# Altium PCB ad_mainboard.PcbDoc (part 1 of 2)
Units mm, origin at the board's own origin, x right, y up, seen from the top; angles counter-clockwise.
Board outline 51.7 x 87.6 mm, 4 copper layers (Top Layer, Layer 1, Layer 2, Bottom Layer), stack 0.568 mm thick; 187 components, 104 nets, 568 pads, 376 vias.
Unrouted connection lines stored in the file: 1.
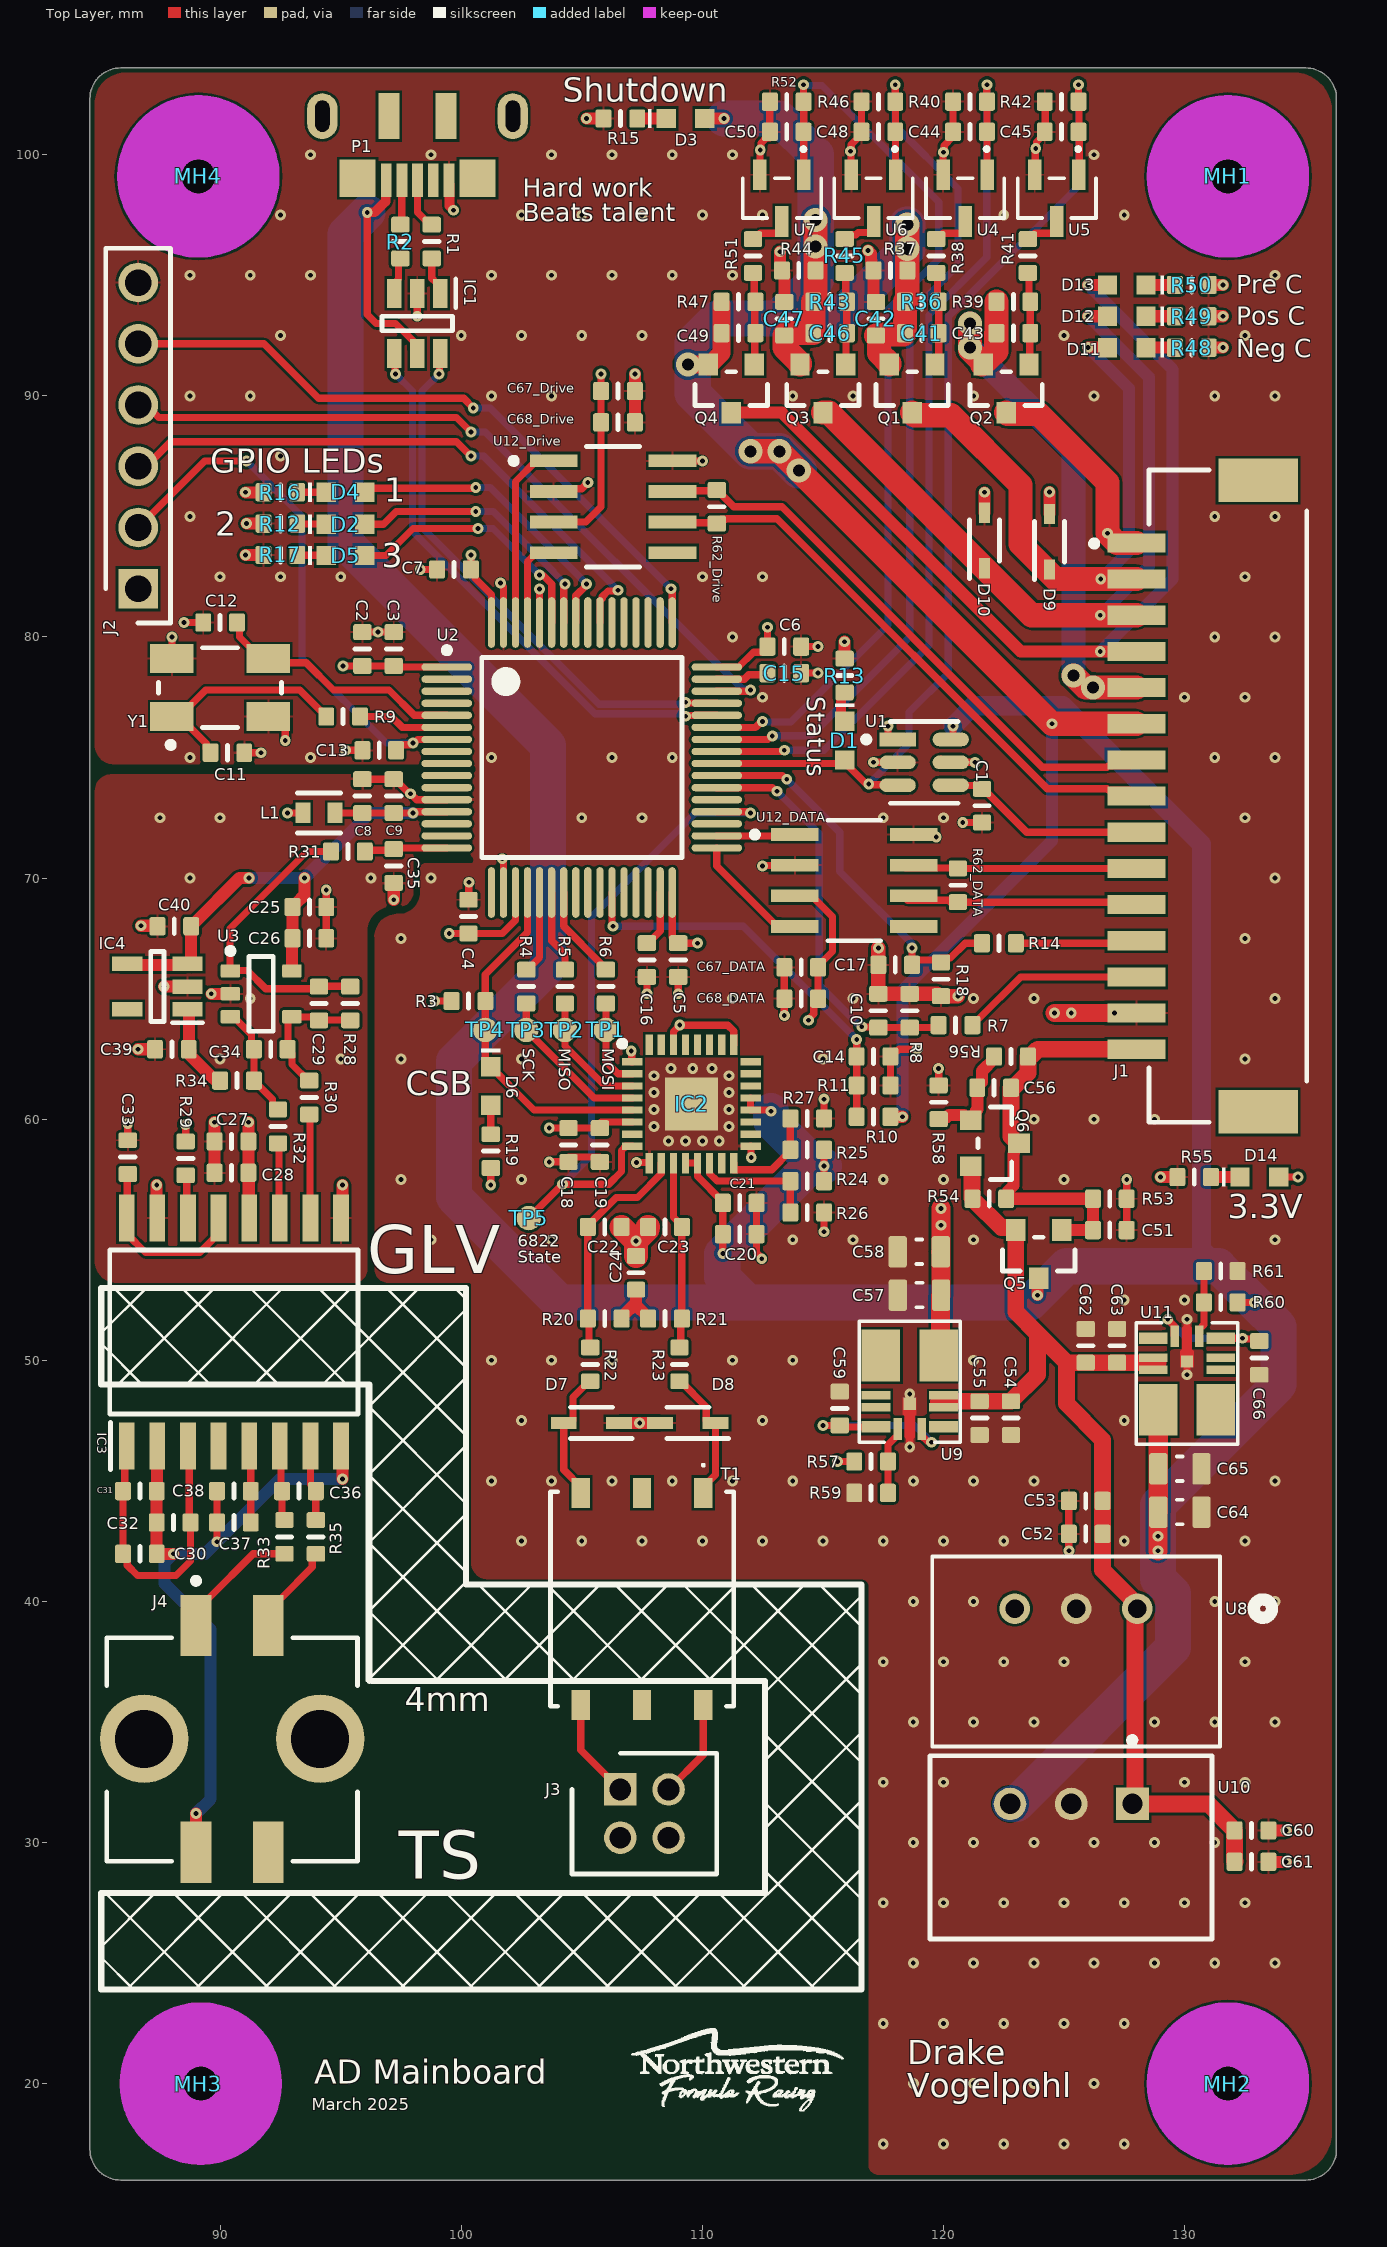
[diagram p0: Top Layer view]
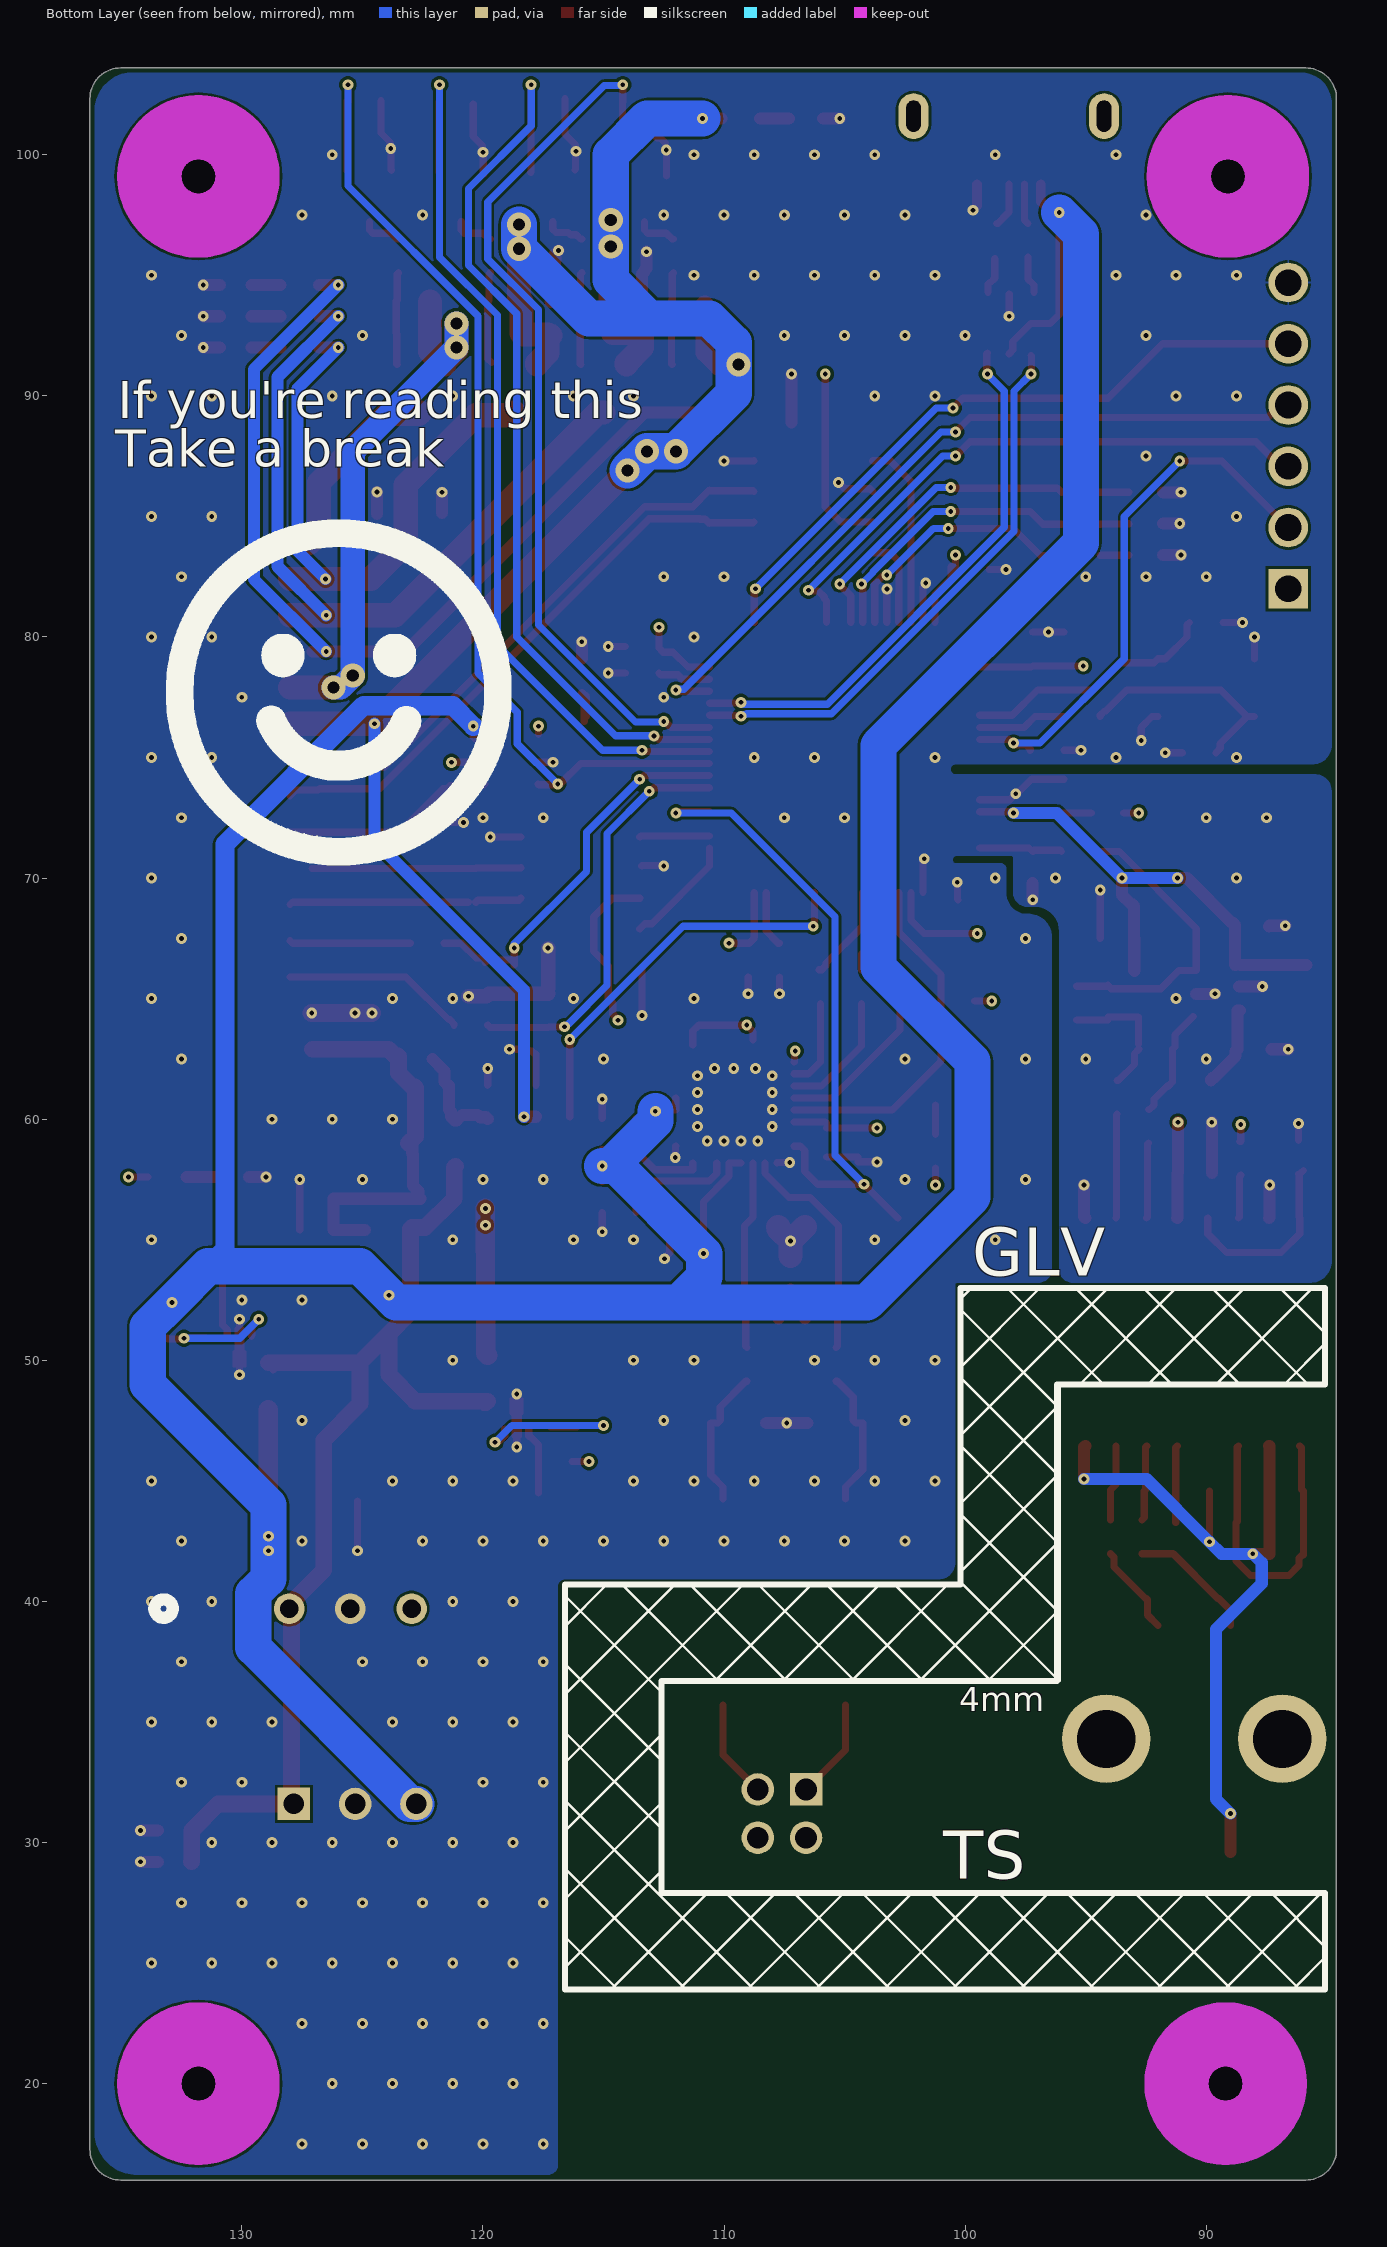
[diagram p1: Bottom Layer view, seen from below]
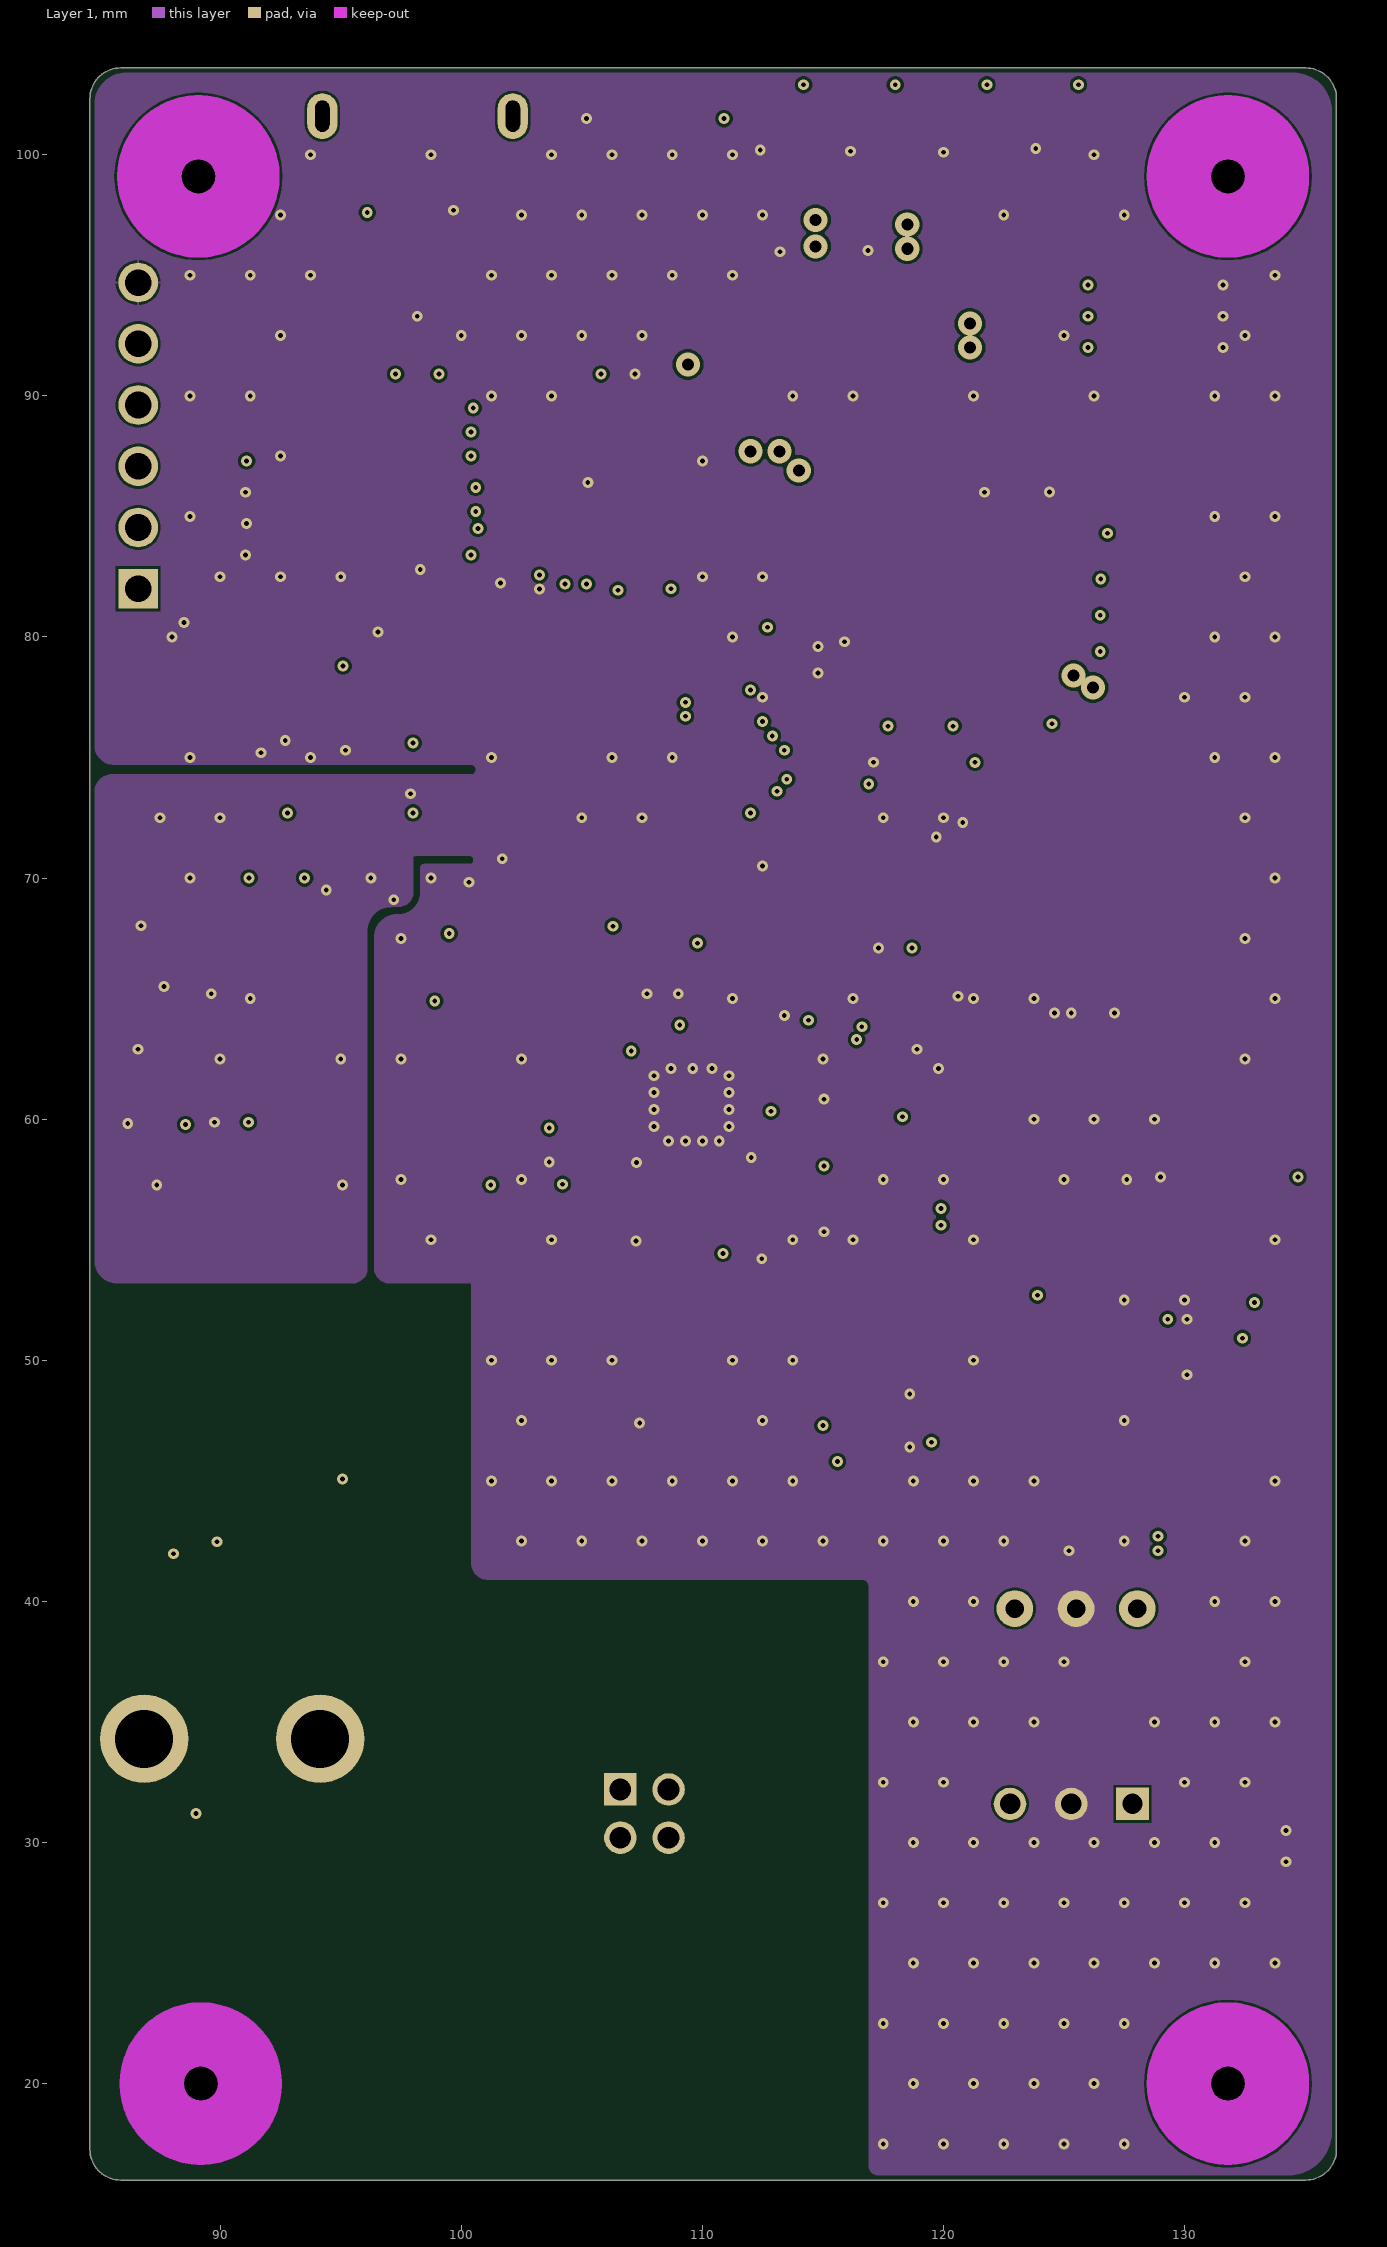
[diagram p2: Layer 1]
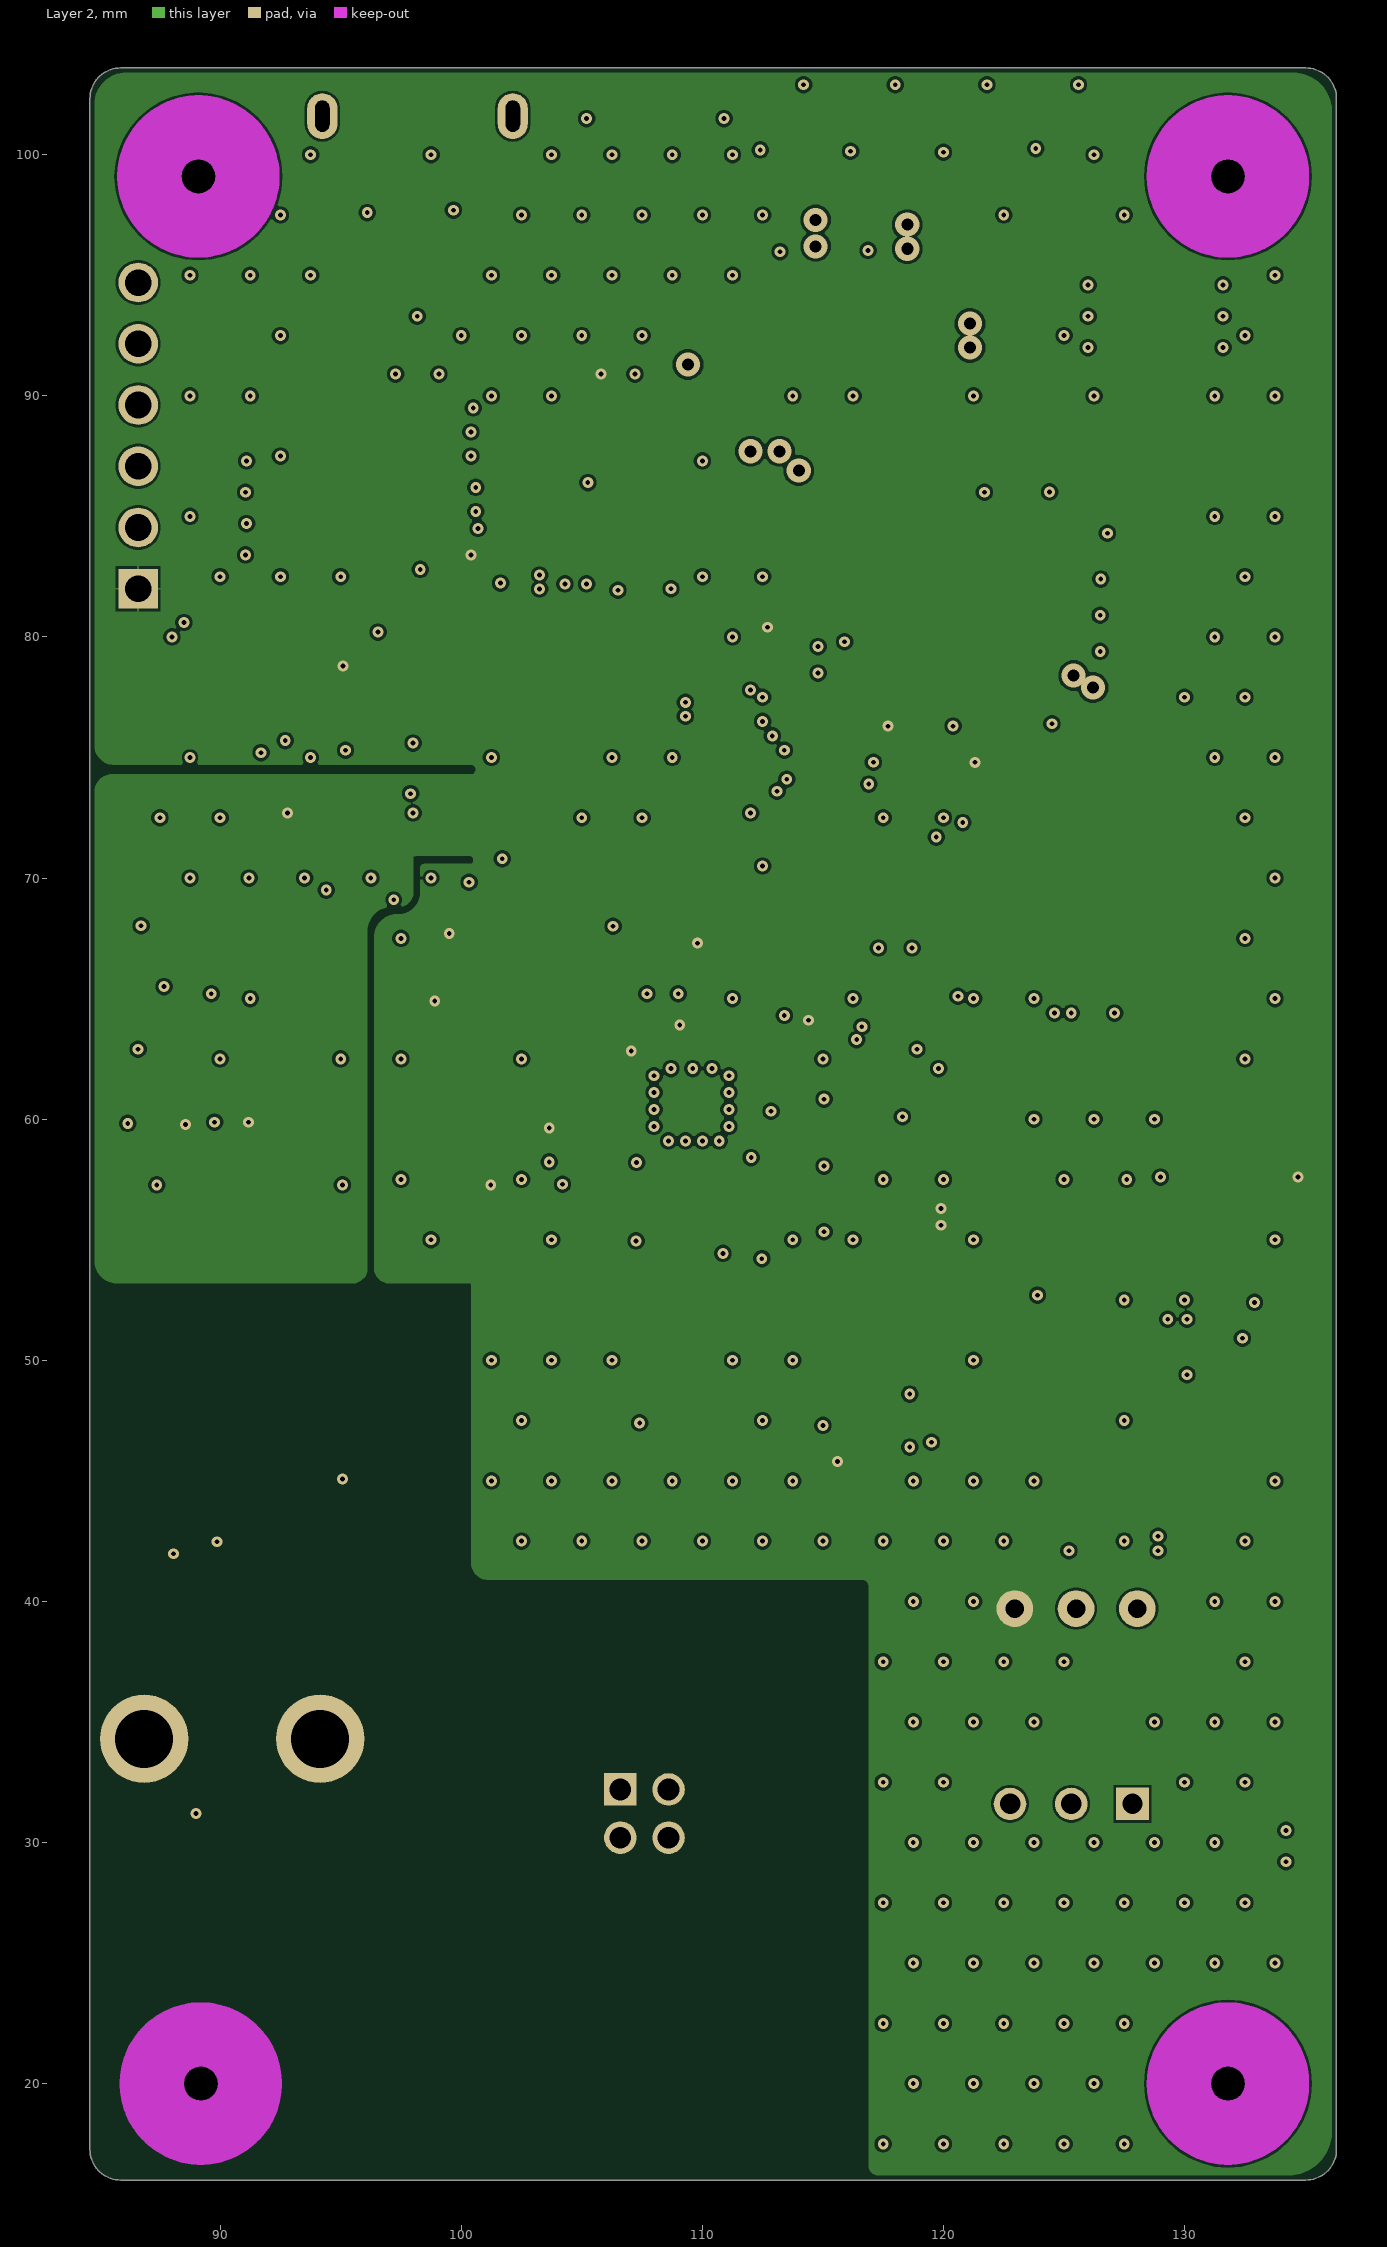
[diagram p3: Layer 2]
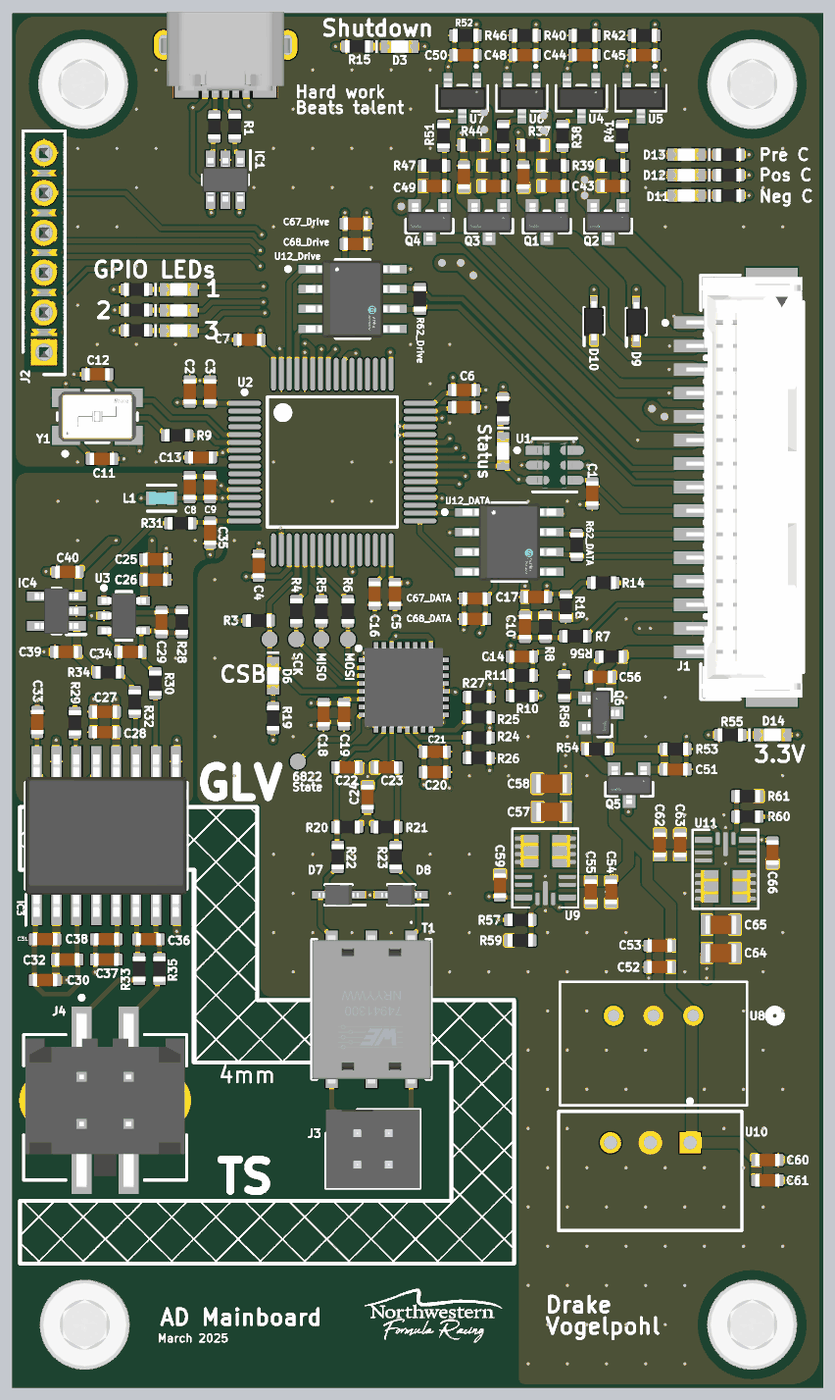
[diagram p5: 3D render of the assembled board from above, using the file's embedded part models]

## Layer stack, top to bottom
Top Solder: solder mask 0.0102, Solder Resist, Dk 3.5
Top Layer: signal copper 0.0356
Dielectric 2: prepreg 0.0711, PP-006, Dk 4.1
Layer 1: signal copper 0.0175
Dielectric 1: dielectric 0.32, FR-4, Dk 4.8
Layer 2: signal copper 0.0175
Dielectric 3: prepreg 0.0711, PP-006, Dk 4.1
Bottom Layer: signal copper 0.0356
Bottom Solder: solder mask 0.0102, Solder Resist, Dk 3.5

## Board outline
84.6,17.27 84.6,102.33 cw(c85.87,102.33) 85.87,103.6 135.03,103.6 cw(c135.03,102.33) 136.3,102.33 136.3,17.27 cw(c135.03,17.27) 135.03,16 85.87,16 cw(c85.87,17.27)

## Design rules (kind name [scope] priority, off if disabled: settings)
BoardOutlineClearance [All] p1: gap=0.2 ignorepadtopadclearanceinfootprint=FALSE
Clearance [All] p1: gap=0.102 ignorepadtopadclearanceinfootprint=FALSE except(0.127: Arc-Via Track-Via SMDPad-Via THPad-Via Via-Via Via-Fill Via-Poly Via-Region Via-Text; 0.25: Arc-Hole Track-Hole SMDPad-Hole THPad-Hole Via-Hole Fill-Hole Poly-Hole Region-Hole Text-Hole)
ComponentClearance [All] p1: gap=0.102 collisioncheckmode=3 verticalgap=0.102 showdistances=TRUE
DiffPairsRouting [All] p1: maxlimit=0.102 minlimit=0.102 mostfreqgap=0.102 toplayer_minwidth=0.102 toplayer_maxwidth=1816.048 toplayer_prefwidth=0.102 midlayer1_minwidth=0.102 midlayer1_maxwidth=1816.048 midlayer1_prefwidth=0.102 midlayer2_minwidth=0.102 midlayer2_maxwidth=1816.048 midlayer2_prefwidth=0.102 bottomlayer_minwidth=0.102 bottomlayer_maxwidth=1816.048 bottomlayer_prefwidth=0.102 maxuncoupledlength=12.7
Height [All] p1: minheight=0 maxheight=1816.048 prefheight=12.7
HoleSize [All] p1: absolutevalues=TRUE maxlimit=6.3 minlimit=0.2 maxpercent=80.000 minpercent=20.000
HoleToHoleClearance [All] p1: gap=0.25 allowstackedmicrovias=FALSE
MinimumAnnularRing [All] p1: minimumring=0.076
MinimumSolderMaskSliver [All] p1: minsoldermaskwidth=0
PlaneClearance [All] p1: clearance=0.102
PlaneConnect PlaneConnectPowerPads [InPadClass('PowerPads')] p1: planeconnectstyle=Direct reliefexpansion=0.508 reliefentries=4 reliefconductorwidth=0.254 reliefairgap=0.254
PlaneConnect [All] p2: pad.planeconnectstyle=Relief pad.reliefexpansion=0.3 pad.reliefentries=4 pad.reliefconductorwidth=0.102 pad.reliefairgap=0.102 via.planeconnectstyle=Direct via.reliefexpansion=0.3 via.reliefentries=4 via.reliefconductorwidth=0.127 via.reliefairgap=0.127
PolygonConnect PolygonConnectPowerPads [All vs (InPadClass('PowerPads'))] p1: connectstyle=Direct reliefconductorwidth=0.254 reliefentries=4 polygonreliefangle="90 Angle" airgapwidth=0.254
PolygonConnect [All] p2: thpad.connectstyle=Relief thpad.reliefconductorwidth=0.102 thpad.reliefentries=4 thpad.polygonreliefangle="90 Angle" thpad.airgapwidth=0.102 smdpad.connectstyle=Relief smdpad.reliefconductorwidth=0.102 smdpad.reliefentries=4 smdpad.polygonreliefangle="90 Angle" smdpad.airgapwidth=0.102 via.connectstyle=Direct via.reliefconductorwidth=0.127 via.reliefentries=4 via.polygonreliefangle="90 Angle" via.airgapwidth=0.127
RoutingVias [All] p1: holewidth=0.2 width=0.45 viastyle="Through Hole" minholewidth=0.2 minwidth=0.45 maxholewidth=6.3 maxwidth=6.55
SilkToSilkClearance [All] p1: silktosilkclearance=0
SilkToSolderMaskClearance [IsPad] p1: minsilkscreentomaskgap=0.102 clearancetoexposedcopper=TRUE
SolderMaskExpansion [All] p1: expansion=0.075 istentingtop=FALSE
SupplyNets "Schematic Supply Nets_5" [InNet('1V25')] p1: voltage=0.000
SupplyNets "Schematic Supply Nets_3" [InNet('3V3')] p2: voltage=0.000
SupplyNets "Schematic Supply Nets_2" [InNet('GND')] p3: voltage=0.000
SupplyNets "Schematic Supply Nets_1" [InNet('5V')] p4: voltage=0.000
SupplyNets "Schematic Supply Nets" [InNet('3V3A')] p5: voltage=0.000
Width [All] p1: maxlimit=1816.048 minlimit=0.102 preferedwidth=0.3 toplayer_minwidth=0.102 minimp=50.000000 maximp=50.000000 favimp=50.000000
20 further rules are at their usual default settings.

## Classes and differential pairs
channel class 6_CAN: DATA Drive
component class "Voltage Regulation": C51 C52 C53 C54 C55 C56 C57 C58 C59 C60 C61 C62 C63 C64 C65 C66 D14 Q5 Q6 R53 R54 R55 R56 R57 R58 R59 R60 R61 U8 U11
component class MCU: C2 C3 C4 C5 C6 C7 C8 C9 C10 C11 C12 C13 C14 C15 C16 C17 D1 D2 D3 D4 D5 L1 R3 R4 R5 R6 R7 R8 R9 R10 R11 R12 R13 R14 R15 R16 R17 R18 TP1 TP2 TP3 TP4 TP5 U2 Y1
component class Drive: C67_Drive C68_Drive CAN1_Drive R62_Drive U12_Drive
component class Designator: C25 C26 C27 C28 C29 C30 C31 C32 C33 C34 C35 C36 C37 C38 C39 C40 IC3 IC4 R28 R29 R30 R31 R32 R33 R34 R35 U3
component class "Daughterboard Comms": C18 C19 C20 C21 C22 C23 C24 D6 D7 D8 IC2 R19 R20 R21 R22 R23 R24 R25 R26 R27 T1
component class DATA: C67_DATA C68_DATA CAN1_DATA R62_DATA U12_DATA
component class "Contactor Control": C41 C42 C43 C44 C45 C46 C47 C48 C49 C50 D9 D10 D11 D12 D13 Q1 Q2 Q3 Q4 R36 R37 R38 R39 R40 R41 R42 R43 R44 R45 R46 R47 R48 R49 R50 R51 R52 U5 U7
component class 0_ADI_BMS_Main_Overview: C1 IC1 J1 J2 J3 J4 MH1 MH2 MH3 MH4 P1 R1 R2 U1
differential pair USB_D: +USB_D_P -USB_D_N

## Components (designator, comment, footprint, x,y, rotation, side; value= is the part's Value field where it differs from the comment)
C1 "CGA3E2X7R1H104K080AA" CAPC0603(1608)100_L 121.6,73 r270 top value=100nF
C2 "GRT188R6YA475KE13D" CAPC0603(1608)100_L 95.9,79.5 r270 top value=4.7µF
C3 "CGA3E2X7R1H104K080AA" CAPC0603(1608)100_L 97.2,79.5 r90 top value=100nF
C4 "CGA3E2X7R1H104K080AA" CAPC0603(1608)100_L 100.3,68.4 r90 top value=100nF
C5 "CGA3E2X7R1H104K080AA" CAPC0603(1608)100_L 109,66.6 r270 top value=100nF
C6 "CGA3E2X7R1H104K080AA" CAPC0603(1608)100_L 113.4,79.6 r0 top value=100nF
C7 "CGA3E2X7R1H104K080AA" CAPC0603(1608)100_L 99.7,82.8 r180 top value=100nF
C8 "GRT188R61H105KE13D" CAPC0603(1608)100_L 95.9,73.4 r270 top value=1µF
C9 "1nF" CAPC0603(1608)100_L 97.2,73.4 r270 top
C10 "CGA3E2X7R1H104K080AA" CAPC0603(1608)100_L 117.3,64.5 r90 top value=100nF
C11 "CL10C150JB81PNC" CAPC0603(1608)100_L 90.3,75.2 r180 top value=15pF
C12 "CL10C150JB81PNC" CAPC0603(1608)100_L 90,80.6 r0 top value=15pF
C13 "CGA3E2X7R1H104K080AA" CAPC0603(1608)100_L 96.6,75.3 r180 top value=100nF
C14 "CGA3E2X7R1H104K080AA" CAPC0603(1608)100_L 117.1,62.6 r0 top value=100nF
C15 "CL10Y225KP84PNC" CAPC0603(1608)100_L 113.4,78.5 r0 top value=2.2µF
C16 "CL10Y225KP84PNC" CAPC0603(1608)100_L 107.7,66.6 r270 top value=2.2µF
C17 "CGA3E2X7R1H104K080AA" CAPC0603(1608)100_L 118,66.4 r180 top value=100nF
C18 "GRT188R6YA475KE13D" CAPC0603(1608)100_L 104.45,58.93 r90 top value=4.7µF
C19 "CGA3E2X7R1H104K080AA" CAPC0603(1608)100_L 105.75,58.93 r270 top value=100nF
C20 "GRT188R6YA475KE13D" CAPC0603(1608)100_L 111.55,55.23 r180 top value=4.7µF
C21 "CGA3E2X7R1H104K080AA" CAPC0603(1608)100_L 111.55,56.53 r0 top value=100nF
C22 "CGA3E2C0G2A221J080AA" CAPC0603(1608)100_L 105.95,55.53 r0 top value=220pF
C23 "CGA3E2C0G2A221J080AA" CAPC0603(1608)100_L 108.45,55.53 r0 top value=220pF
C24 "CGA3E2X7R1H104K080AA" CAPC0603(1608)100_L 107.25,53.63 r90 top value=100nF
C25 "GRT188R61H105KE13D" CAPC0603(1608)100_L 93.7,68.8 r180 top value=1µF
C26 "1nF" CAPC0603(1608)100_L 93.7,67.5 r180 top
C27 "GRT188R61H105KE13D" CAPC0603(1608)100_L 90.47,59.075 r0 top value=1µF
C28 "1nF" CAPC0603(1608)100_L 90.47,57.775 r0 top
C29 "1nF" CAPC0603(1608)100_L 94.1,64.8 r90 top
C30 "GRT188R61H105KE13D" CAPC0603(1608)100_L 86.67,41.975 r180 top value=1µF
C31 "1 nF" CAPC0603(1608)100_L 86.67,44.575 r180 top
C32 "CGA3E2X7R1H104K080AA" CAPC0603(1608)100_L 88.07,43.275 r0 top value=100nF
C33 "CGA3E2X7R1H104K080AA" CAPC0603(1608)100_L 86.17,58.425 r90 top value=100nF
C34 "1nF" CAPC0603(1608)100_L 92.1,62.9 r0 top
C35 "GRT188R61H105KE13D" CAPC0603(1608)100_L 97.2,70.5 r90 top value=1µF
C36 "GCM188R72A103KA37D" CAPC0603(1608)100_L 93.27,44.575 r180 top value=10nF
C37 "CGA3E2X7R1H104K080AA" CAPC0603(1608)100_L 90.57,43.275 r180 top value=100nF
C38 "1 nF" CAPC0603(1608)100_L 90.57,44.575 r0 top
C39 "GRT188R61H105KE13D" CAPC0603(1608)100_L 88,62.9 r0 top value=1µF
C40 "GRT188R61H105KE13D" CAPC0603(1608)100_L 88.1,68 r0 top value=1µF
C41 "CGA3E2X7R1H104K080AA" CAPC0603(1608)100_L 119.1,92.602 r180 top value=100nF
C42 "GRM188R6YA106MA73D" CAPC0603(1608)100_L 117.2,93.2 r270 top value=10µF
C43 "CGA3E2X7R1H104K080AA" CAPC0603(1608)100_L 122.9,92.602 r180 top value=100nF
C44 "CGA3E2X7R1H104K080AA" CAPC0603(1608)100_L 121.1,100.95 r0 top value=100nF
C45 "CGA3E2X7R1H104K080AA" CAPC0603(1608)100_L 124.9,100.95 r0 top value=100nF
C46 "CGA3E2X7R1H104K080AA" CAPC0603(1608)100_L 115.3,92.602 r180 top value=100nF
C47 "GRM188R6YA106MA73D" CAPC0603(1608)100_L 113.4,93.2 r270 top value=10µF
C48 "CGA3E2X7R1H104K080AA" CAPC0603(1608)100_L 117.3,100.95 r0 top value=100nF
C49 "CGA3E2X7R1H104K080AA" CAPC0603(1608)100_L 111.5,92.602 r180 top value=100nF
C50 "CGA3E2X7R1H104K080AA" CAPC0603(1608)100_L 113.5,100.95 r0 top value=100nF
C51 "CGA3E2X7R1H104K080AA" CAPC0603(1608)100_L 126.9,55.4 r0 top value=100nF
C52 "GRT188R6YA475KE13D" CAPC0603(1608)100_L 125.9,42.8 r0 top value=4.7µF
C53 "CGA3E2X7R1H104K080AA" CAPC0603(1608)100_L 125.9,44.168 r180 top value=100nF
C54 "GRT188R6YA475KE13D" CAPC0603(1608)100_L 122.8,47.6 r90 top value=4.7µF
C55 "CGA3E2X7R1H104K080AA" CAPC0603(1608)100_L 121.5,47.6 r270 top value=100nF
C56 "CGA3E2X7R1H104K080AA" CAPC0603(1608)100_L 122.1,61.3 r180 top value=100nF
C57 "CL21A226MAYNNNE" CAPC0805(2012)145_L 119.01,52.7 r0 top value=22µF
C58 "CL21A226MAYNNNE" CAPC0805(2012)145_L 119,54.5 r0 top value=22µF
C59 "GRT188R61H105KE13D" CAPC0603(1608)100_L 115.7,48 r270 top value=1µF
C60 "GRT188R6YA475KE13D" CAPC0603(1608)100_L 132.775,30.5 r180 top value=4.7µF
C61 "CGA3E2X7R1H104K080AA" CAPC0603(1608)100_L 132.775,29.2 r0 top value=100nF
C62 "GRT188R6YA475KE13D" CAPC0603(1608)100_L 125.9,50.6 r270 top value=4.7µF
C63 "CGA3E2X7R1H104K080AA" CAPC0603(1608)100_L 127.2,50.6 r90 top value=100nF
C64 "CL21A226MAYNNNE" CAPC0805(2012)145_L 129.8,43.7 r180 top value=22µF
C65 "CL21A226MAYNNNE" CAPC0805(2012)145_L 129.8,45.5 r180 top value=22µF
C66 "GRT188R61H105KE13D" CAPC0603(1608)100_L 133.1,50.1 r90 top value=1µF
C67_DATA "GRT188R6YA475KE13D" CAPC0603(1608)100_L 114.1,66.3 r0 top value=4.7µF (schematic designator C67)
C67_Drive "GRT188R6YA475KE13D" CAPC0603(1608)100_L 106.5,90.2 r180 top value=4.7µF (schematic designator C67)
C68_DATA "CGA3E2X7R1H104K080AA" CAPC0603(1608)100_L 114.1,65 r180 top value=100nF (schematic designator C68)
C68_Drive "CGA3E2X7R1H104K080AA" CAPC0603(1608)100_L 106.5,88.9 r0 top value=100nF (schematic designator C68)
D1 "150060RS75000" WL-SMCW_0603_150060xx75000 115.9,75.7 r270 top
D2 "150060YS75000" WL-SMCW_0603_150060xx75000 95.2,84.675 r0 top
D3 "150060RS75000" WL-SMCW_0603_150060xx75000 109.3,101.5 r0 top
D4 "150060YS75000" WL-SMCW_0603_150060xx75000 95.2,86 r0 top
D5 "150060YS75000" WL-SMCW_0603_150060xx75000 95.2,83.375 r0 top
D6 "150060YS75000" WL-SMCW_0603_150060xx75000 101.225,61.375 r270 top
D7 "SD12C-01FTG" SOD2613X114N 105.4,47.4 r180 top
D8 "SD12C-01FTG" SOD2613X114N 109.4,47.4 r180 top
D9 "PMEG6010CEJ,115" SODFL2512X80N 124.4,83.95 r90 top
D10 "PMEG6010CEJ,115" SODFL2512X80N 121.7,84 r90 top
D11 "150060BS75000" WL-SMCW_0603_150060xx75000 127.6,92 r180 top
D12 "150060BS75000" WL-SMCW_0603_150060xx75000 127.6,93.3 r180 top
D13 "150060BS75000" WL-SMCW_0603_150060xx75000 127.6,94.6 r180 top
D14 "150060VS75000" WL-SMCW_0603_150060xx75000 133.1,57.6 r0 top
IC1 "USBLC6-2SC6" SOT95P280X145-6N 98.175,93 r270 top
IC2 "ADBMS6822WCCSZ" QFN50P500X500X80-33N-D 109.55,60.63 r0 top
IC3 "AMC3302DWE" SOIC127P1030X265-16N 90.57,51.175 r90 top
IC4 "REF2025AIDDCR" SOT95P280X110-5N 87.4,65.5 r180 top
J1 "502584-1570" FP-502584-1570-MFG 131.795,73.4 r90 top
J2 "61300611121" HDRV6W64P0X254_1X6_1524X254X869P 86.6,82 r90 top
J3 "DF11-4DP-2DSA_01_" SHDR4W50P200_2X2_600X500X660P 106.6,32.2 r180 top
J4 "43045-0415" FP-43045-0415-MFG 90.5,33.855 r180 top
L1 "LQW18AN39NJ00D" FP-LQW18AN_00-MFG 94.1,72.7 r0 top
MH1 "Mounting Hole 6-32 Non Plated" "Mounting Hole 6-32-Footprint-1"#1 131.8,99.1 r0 top
MH2 "Mounting Hole 6-32 Non Plated" "Mounting Hole 6-32-Footprint-1"#1 131.8,20 r0 top locked
MH3 "Mounting Hole 6-32 Non Plated" "Mounting Hole 6-32-Footprint-1"#2 89.2,20 r0 top locked
MH4 "Mounting Hole 6-32 Non Plated" "Mounting Hole 6-32-Footprint-1"#1 89.1,99.1 r0 top locked
P1 "1051640001" 1051640001-Footprint-1 98.188,103.05 r0 top
Q1 "DMP3056L-7" FP-SOT23-MFG 118.7,90.302 r270 top
Q2 "DMP3056L-7" FP-SOT23-MFG 122.6,90.302 r270 top
Q3 "DMP3056L-7" FP-SOT23-MFG 115,90.302 r270 top
Q4 "DMP3056L-7" FP-SOT23-MFG 111.2,90.302 r270 top
Q5 "DMP3056L-7" FP-SOT23-MFG 123.95,54.4 r270 top
Q6 "DMP3056L-7" FP-SOT23-MFG 122.132,59 r0 top
R1 "RC0603FR-0722RL" RESC0603(1608)_L 98.775,96.4 r270 top value=22
R2 "RC0603FR-0722RL" RESC0603(1608)_L 97.475,96.4 r270 top value=22
R3 "RT0603BRD0710KL" RESC0603(1608)_L 100.3,64.9 r180 top value=DNP
R4 "RMCF0603FT10R0" RESC0603(1608)_L 102.7,65.5 r90 top value=10
R5 "RMCF0603FT10R0" RESC0603(1608)_L 104.3,65.5 r90 top value=10
R6 "RMCF0603FT10R0" RESC0603(1608)_L 106,65.5 r90 top value=10
R7 "ERA-3AEB473V" RESC0603(1608)_L 120.5,63.9 r0 top value=47k
R8 "ERA-3AEB622V" RESC0603(1608)_L 118.6,64.5 r90 top value=6.2k
R9 "RMCF0603ZT0R00" RESC0603(1608)_L 95.1,76.7 r0 top value=0
R10 "ERJ-3EKF1003V" RESC0603(1608)_L 117.1,60.1 r180 top value=100k
R11 "ERA-3AEB153V" RESC0603(1608)_L 117.1,61.4 r180 top value=15k
R12 "RMCF0603FT1K00" RESC0603(1608)_L 92.5,84.7 r0 top value=1k
R13 "RMCF0603FT1K00" RESC0603(1608)_L 115.9,78.4 r270 top value=1k
R14 "ERA-3AEB332V" RESC0603(1608)_L 122.3,67.3 r0 top value=3.3k
R15 "RT0603BRD0710KL" RESC0603(1608)_L 106.6,101.5 r0 top value=10k
R16 "RMCF0603FT1K00" RESC0603(1608)_L 92.5,86 r0 top value=1k
R17 "RMCF0603FT1K00" RESC0603(1608)_L 92.5,83.4 r0 top value=1k
R18 "RT0603BRD0710KL" RESC0603(1608)_L 119.9,65.8 r90 top value=10k
R19 "RMCF0603FT1K00" RESC0603(1608)_L 101.225,58.675 r270 top value=1k
R20 "ESR03EZPJ470" RESC0603(1608)_L 105.95,51.73 r180 top value=47
R21 "ESR03EZPJ470" RESC0603(1608)_L 108.45,51.73 r180 top value=47
R22 "ESR03EZPJ470" RESC0603(1608)_L 105.35,49.83 r90 top value=47
R23 "ESR03EZPJ470" RESC0603(1608)_L 109.05,49.83 r90 top value=47
R24 "RMCF0603ZT0R00" RESC0603(1608)_L 114.35,57.43 r0 top value=DNP
R25 "RMCF0603ZT0R00" RESC0603(1608)_L 114.35,58.73 r0 top value=DNP
R26 "RMCF0603ZT0R00" RESC0603(1608)_L 114.35,56.13 r0 top value=0
R27 "RMCF0603ZT0R00" RESC0603(1608)_L 114.35,60.03 r180 top value=0
R28 "ERA-3AEB203V" RESC0603(1608)_L 95.4,64.8 r90 top value=20k
R29 "ERA-3AEB473V" RESC0603(1608)_L 88.57,58.375 r90 top value=47k
R30 "RT0603BRD0710KL" RESC0603(1608)_L 93.7,60.9 r90 top value=10k
R31 "RMCF0603FT1K00" RESC0603(1608)_L 95.3,71.1 r180 top value=1k
R32 "RT0603BRD0710KL" RESC0603(1608)_L 92.4,59.7 r90 top value=10k
R33 "RMCF0603FT10R0" RESC0603(1608)_L 92.67,42.675 r90 top value=10
R34 "ERA-3AEB203V" RESC0603(1608)_L 90.7,61.6 r0 top value=20k
R35 "RMCF0603FT10R0" RESC0603(1608)_L 93.97,42.675 r90 top value=10
R36 "ERA-3AEB473V" RESC0603(1608)_L 119.1,93.902 r180 top value=47k
R37 "RT0603BRD0710KL" RESC0603(1608)_L 117.8,95.2 r0 top value=10k
R38 "RT0603BRD0710KL" RESC0603(1608)_L 119.7,95.802 r270 top value=10k
R39 "ERA-3AEB473V" RESC0603(1608)_L 122.9,93.902 r180 top value=47k
R40 "ERA-3AEB473V" RESC0603(1608)_L 121.1,102.202 r0 top value=47k
R41 "RT0603BRD0710KL" RESC0603(1608)_L 123.5,95.8 r270 top value=10k
R42 "ERA-3AEB473V" RESC0603(1608)_L 124.9,102.202 r0 top value=47k
R43 "ERA-3AEB473V" RESC0603(1608)_L 115.3,93.902 r180 top value=47k
R44 "RT0603BRD0710KL" RESC0603(1608)_L 114,95.2 r0 top value=10k
R45 "RT0603BRD0710KL" RESC0603(1608)_L 115.9,95.802 r270 top value=10k
R46 "ERA-3AEB473V" RESC0603(1608)_L 117.3,102.202 r0 top value=47k
R47 "ERA-3AEB473V" RESC0603(1608)_L 111.5,93.902 r180 top value=47k
R48 "RT0603BRD0710KL" RESC0603(1608)_L 130.3,92 r180 top value=10k
R49 "RT0603BRD0710KL" RESC0603(1608)_L 130.3,93.3 r180 top value=10k
R50 "RT0603BRD0710KL" RESC0603(1608)_L 130.3,94.6 r180 top value=10k
R51 "RT0603BRD0710KL" RESC0603(1608)_L 112.1,95.802 r270 top value=10k
R52 "ERA-3AEB473V" RESC0603(1608)_L 113.5,102.202 r0 top value=47k
R53 "ERA-3AEB473V" RESC0603(1608)_L 126.9,56.7 r180 top value=47k
R54 "RMCF0603ZT0R00" RESC0603(1608)_L 121.9,56.7 r0 top value=DNP
R55 "RMCF0603FT1K00" RESC0603(1608)_L 130.4,57.6 r0 top value=1k
R56 "RT0603BRD0710KL" RESC0603(1608)_L 122.8,62.6 r0 top value=10k
R57 "RT0603BRD0723K2L" RESC0603(1608)_L 117,45.8 r180 top value=23.2k
R58 "ERA-3AEB473V" RESC0603(1608)_L 119.8,60.7 r270 top value=47k
R59 "RT0603BRD0710KL" RESC0603(1608)_L 117,44.5 r0 top value=10k
R60 "RT0603BRD0740K2L" RESC0603(1608)_L 131.5,52.4 r0 top value=40.2k
R61 "RT0603BRD0710KL" RESC0603(1608)_L 131.5,53.7 r180 top value=10k
R62_DATA "DNP" RESC0603(1608)_L 120.6,69.7 r90 top value=120 (schematic designator R62)
R62_Drive "DNP" RESC0603(1608)_L 110.6,85.4 r90 top value=120 (schematic designator R62)
T1 "74941300" 74941300 107.5,40.1 r180 top
TP1 "TEST_POINT_40_MIL" TEST_POINT_40_MIL-Footprint-1#1 106.1,63.7 r180 top
TP2 "TEST_POINT_40_MIL" TEST_POINT_40_MIL-Footprint-1#2 104.3,63.7 r180 top
TP3 "TEST_POINT_40_MIL" TEST_POINT_40_MIL-Footprint-1#2 102.7,63.7 r180 top
TP4 "TEST_POINT_40_MIL" TEST_POINT_40_MIL-Footprint-1#2 101,63.7 r180 top
TP5 "TEST_POINT_40_MIL" TEST_POINT_40_MIL-Footprint-1#2 102.8,55.9 r0 top
U1 "SN74LVC1T45DBVR" FP-DBV0006A-IPC_B 119.2,74.8 r0 top
U2 "STM32F405RGT6" STM-LQFP64_M 105,75 r0 top locked
U3 "OPA320AIDBVR" DBV0005A_L 91.7,65.2 r0 top
U4 "DMN62D0U-7" SOT23_DMN62D0U-7_DIO 120.9,98.2 r180 top
U5 "DMN62D0U-7" SOT23_DMN62D0U-7_DIO 124.7,98.2 r180 top
U6 "DMN62D0U-7" SOT23_DMN62D0U-7_DIO 117.1,98.2 r180 top
U7 "DMN62D0U-7" SOT23_DMN62D0U-7_DIO 113.3,98.2 r180 top
U8 "TSR 1-2433" TSR1-SINGLE_TRP 128.04,39.7 r180 top
U9 "TPSM33625FRDNR" TPSM33625FRDNR 118.6,49.2 r180 top
U10 "TSR 1-2450" TRACO-SIP-3_V 125.3,31.6 r180 top
U11 "TPSM33625FRDNR" TPSM33625FRDNR 130.1,48.95 r0 top
U12_DATA "MAX3051ESA+" FP-S8-4-MFG 116.3,69.9 r0 top (schematic designator U12)
U12_Drive "MAX3051ESA+" FP-S8-4-MFG 106.3,85.4 r0 top (schematic designator U12)
Y1 "ABM3B-8.000MHZ-10-1-U-T" FP-ABM3B-MFG 90,77.9 r0 top

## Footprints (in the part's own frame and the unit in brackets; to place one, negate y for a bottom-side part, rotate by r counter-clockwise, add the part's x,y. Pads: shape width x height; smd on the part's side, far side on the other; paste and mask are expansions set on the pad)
74941300 [mm]
  rect 0.76x1.25 smd: 1(-2.54,-4.4) 2(0,-4.4) 3(2.54,-4.4) 4(2.54,4.4) 5(0,4.4) 6(-2.54,4.4)
  silkscreen extent -3.8,-5.6 3.8,4.45, body extent -3.8,-4.72 3.8,4.72, height 5.41
1051640001-Footprint-1 [mm]
  rect 0.45x1.38 smd mask+0.12: 1(-1.3,-4.11) 2(-0.65,-4.11) 3(0,-4.11) 4(0.65,-4.11) 5(1.3,-4.11)
  oval 1.25x1.9 hole 0.6 slot 1.3 at 90 deg: 6(-3.95,-1.45) 6(3.95,-1.45)
  rect 1.5x1.55 smd mask+0.12: 6(-2.488,-4.025) 6(2.488,-4.025)
  rect 0.875x1.9 smd: 6(-1.188,-1.45) 6(1.188,-1.45)
  body extent -4.1,-4.51 4.1,0.64, height 2.45
CAPC0603(1608)100_L [mm] "Chip Capacitor, Body 1.6x0.8mm, Height 1.0mm, IPC High Density"
  rrect25% 0.66x0.76 smd: 1(-0.7,0) 2(0.7,0)
  silkscreen extent 0,-0.3 0,0.3, body extent -0.8,-0.4 0.8,0.4, height 0.95
CAPC0805(2012)145_L [mm] "Chip Capacitor, Body 2.0x1.2mm, Height 1.45mm, IPC High Density"
  rrect25% 0.76x1.3 smd: 1(-0.9,0) 2(0.89,0)
  silkscreen extent -0.13,-0.51 0.13,0.51, body extent -1,-0.6 1,0.6, height 1.45
DBV0005A_L [mm] "SOT23, 5-Leads, Body 3.05x1.75mm, Pitch 0.95mm, IPC High Density"
  rrect18% 0.8x0.55 smd: 1(-1.275,0.95) 2(-1.275,0) 3(-1.275,-0.95) 4(1.275,-0.95) 5(1.275,0.95)
  silkscreen extent -1.4,-1.55 0.5,1.9, body extent -1.42,-1.46 1.42,1.46, height 1.08
FP-43045-0415-MFG [mm]
  rect 1.27x2.54 smd paste+0 mask+0: 1(1.5,-5.145) 2(-1.5,-5.145) 3(1.5,4.255) 4(-1.5,4.255)
  round 3.66 hole 2.41 paste-2539.97 mask+0: 5(-3.65,-0.445) 6(3.65,-0.445)
  silkscreen extent -5.2,-7.12 5.2,4.63, body extent -5.58,-6.52 5.58,5.63, height 0.25
FP-502584-1570-MFG [mm]
  rect 0.8x2.4 smd paste+0 mask+0: 1(10.5,3.795) 2(9,3.795) 3(7.5,3.795) 4(6,3.795) 5(4.5,3.795) 6(3,3.795) 7(1.5,3.795) 8(0,3.795) 9(-1.5,3.795) 10(-3,3.795) 11(-4.5,3.795) 12(-6,3.795) 13(-7.5,3.795) 14(-9,3.795) 15(-10.5,3.795)
  rect 1.8x3.3 smd paste+0 mask+0: 16(13.1,-1.255) 17(-13.1,-1.255)
  silkscreen extent -13.52,-3.27 13.52,5.67, body extent -14.1,-3.37 14.1,5.1, height 0.25
FP-ABM3B-MFG [mm]
  rect 1.8x1.2 smd paste+0 mask+0: 1(-2,-1.2) 2(2,-1.2) 3(2,1.2) 4(-2,1.2)
  silkscreen extent -2.55,-2.5 2.55,1.65, body extent -3,-1.9 3,1.9, height 0.25
FP-DBV0006A-IPC_B [mm]
  rect 1.505x0.57 smd paste+0 mask+0: 1(-1.1,0.95)
  rrect100% 1.505x0.57 smd paste+0 mask+0: 2(-1.1,0) 3(-1.1,-0.95) 4(1.1,-0.95) 5(1.1,0) 6(1.1,0.95)
  silkscreen extent -2.53,-1.7 1.4,1.7, body extent -2.1,-1.7 2.1,1.7, height 0.25
FP-LQW18AN_00-MFG [mm]
  rect 0.625x0.85 smd paste+0 mask+0: 1(-0.663,0) 2(0.663,0)
  silkscreen extent -0.9,-0.82 0.9,0.82, body extent -1.07,-0.6 1.07,0.6, height 0.25
FP-S8-4-MFG [mm]
  rect 1.98x0.53 smd paste+0 mask+0: 1(-2.465,1.905) 2(-2.465,0.635) 3(-2.465,-0.635) 4(-2.465,-1.905) 5(2.465,-1.905) 6(2.465,-0.635) 7(2.465,0.635) 8(2.465,1.905)
  silkscreen extent -4.25,-2.5 1.1,2.5, body extent -3.55,-2.75 3.55,2.75, height 0.25
FP-SOT23-MFG [mm]
  rect 0.9x0.8 smd paste+0 mask+0: 1(-1,0.95) 2(-1,-0.95) 3(1,0)
  silkscreen extent -0.7,-1.5 0.7,1.5, body extent -1.55,-1.6 1.55,1.6, height 0.25
HDRV6W64P0X254_1X6_1524X254X869P [mm]
  rect 1.65x1.65 hole 1.1: 1(0,0)
  round 1.65 hole 1.1: 2(2.54,0) 3(5.08,0) 4(7.62,0) 5(10.16,0) 6(12.7,0)
  silkscreen extent -1.42,-1.35 14.12,1.35, body extent -1.27,-1.27 13.97,1.27, height 8.69
"Mounting Hole 6-32-Footprint-1"#1 [mil]
  rrect0% 0x0 hole 149 unplated mask+55: ""(0,0)
  Keep-Out Layer circle w105: c0,0 r80.16
  body extent -113,-113 113,113, height 138
"Mounting Hole 6-32-Footprint-1"#2 [mil]
  rrect0% 0x0 hole 149 unplated mask+55: ""(-3.94,0)
  Keep-Out Layer circle w105: c0,0 r80.16
  body extent -113,-113 113,113, height 138
QFN50P500X500X80-33N-D [mm]
  rect 0.85x0.3 smd: 1(-2.45,1.75) 2(-2.45,1.25) 3(-2.45,0.75) 4(-2.45,0.25) 5(-2.45,-0.25) 6(-2.45,-0.75) 7(-2.45,-1.25) 8(-2.45,-1.75) 17(2.45,-1.75) 18(2.45,-1.25) 19(2.45,-0.75) 20(2.45,-0.25) 21(2.45,0.25) 22(2.45,0.75) 23(2.45,1.25) 24(2.45,1.75)
  rect 0.3x0.85 smd: 9(-1.75,-2.45) 10(-1.25,-2.45) 11(-0.75,-2.45) 12(-0.25,-2.45) 13(0.25,-2.45) 14(0.75,-2.45) 15(1.25,-2.45) 16(1.75,-2.45) 25(1.75,2.45) 26(1.25,2.45) 27(0.75,2.45) 28(0.25,2.45) 29(-0.25,2.45) 30(-0.75,2.45) 31(-1.25,2.45) 32(-1.75,2.45)
  rect 2.2x2.2 smd: 33(0,0)
  silkscreen extent -3,2.38 -2.75,2.62, body extent -2.55,-2.55 2.55,2.55, height 0.8
RESC0603(1608)_L [mm] "Chip Resistor, Body 1.6x0.8mm, IPC High Density"
  rrect25% 0.66x0.76 smd: 1(-0.7,0) 2(0.7,0)
  silkscreen extent 0,-0.3 0,0.3, body extent -0.8,-0.4 0.8,0.4, height 0.45
SHDR4W50P200_2X2_600X500X660P [mm]
  rect 1.35x1.35 hole 0.9: 1(0,0)
  round 1.35 hole 0.9: 2(0,2) 3(-2,0) 4(-2,2)
  silkscreen extent -4,-1.5 2,3.5, body extent -4,-1.5 2,3.5, height 6.6
SOD2613X114N [mm]
  rect 1.075x0.5 smd: 1(-1.15,0) 2(1.15,0)
  silkscreen extent -1.69,-0.65 0.87,0.65, body extent -1.29,-0.65 1.29,0.65, height 1.14
SODFL2512X80N [mm]
  rect 0.84x0.46 smd: 1(-1.15,0) 2(1.15,0)
  silkscreen extent -1.57,-0.63 0.85,0.63, body extent -1.25,-0.63 1.25,0.62, height 0.71
SOIC127P1030X265-16N [mm]
  rect 1.95x0.65 smd: 1(-4.725,4.445) 2(-4.725,3.175) 3(-4.725,1.905) 4(-4.725,0.635) 5(-4.725,-0.635) 6(-4.725,-1.905) 7(-4.725,-3.175) 8(-4.725,-4.445) 9(4.725,-4.445) 10(4.725,-3.175) 11(4.725,-1.905) 12(4.725,-0.635) 13(4.725,0.635) 14(4.725,1.905) 15(4.725,3.175) 16(4.725,4.445)
  silkscreen extent -5.7,-5.15 3.4,5.15, body extent -5.17,-5.15 5.17,5.15, height 2.59
SOT23_DMN62D0U-7_DIO [mil]
  rect 22x50 smd paste+0 mask+0: 1(-36.02,-38.21) 2(36.02,-38.21) 3(0,38.21)
  silkscreen extent -64,-83 64,33, body extent -59,-49 59,49, height 43
SOT95P280X110-5N [mm]
  rect 1.25x0.6 smd: 1(-1.25,0.95) 2(-1.25,0) 3(-1.25,-0.95) 4(1.25,-0.95) 5(1.25,0.95)
  silkscreen extent -1.88,-1.45 0.28,1.5, body extent -1.4,-1.45 1.4,1.45, height 0.97
SOT95P280X145-6N [mm]
  rect 1.2x0.6 smd: 1(-1.25,0.95) 2(-1.25,0) 3(-1.25,-0.95) 4(1.25,-0.95) 5(1.25,0) 6(1.25,0.95)
  silkscreen extent -1.85,-1.46 0.3,1.6, body extent -1.4,-1.46 1.4,1.46, height 1.45
STM-LQFP64_M [mm] "Thin QFP, 64-Leads, Body 10x10mm, Pitch 0.5mm, IPC Low Density"
  oval 2.1x0.3 smd: 1(-5.6,3.75) 2(-5.6,3.25) 3(-5.6,2.75) 4(-5.6,2.25) 5(-5.6,1.75) 6(-5.6,1.25) 7(-5.6,0.75) 8(-5.6,0.25) 9(-5.6,-0.25) 10(-5.6,-0.75) 11(-5.6,-1.25) 12(-5.6,-1.75) 13(-5.6,-2.25) 14(-5.6,-2.75) 15(-5.6,-3.25) 16(-5.6,-3.75) 33(5.6,-3.75) 34(5.6,-3.25) 35(5.6,-2.75) 36(5.6,-2.25) 37(5.6,-1.75) 38(5.6,-1.25) 39(5.6,-0.75) 40(5.6,-0.25) 41(5.6,0.25) 42(5.6,0.75) 43(5.6,1.25) 44(5.6,1.75) 45(5.6,2.25) 46(5.6,2.75) 47(5.6,3.25) 48(5.6,3.75)
  oval 0.3x2.1 smd: 17(-3.75,-5.6) 18(-3.25,-5.6) 19(-2.75,-5.6) 20(-2.25,-5.6) 21(-1.75,-5.6) 22(-1.25,-5.6) 23(-0.75,-5.6) 24(-0.25,-5.6) 25(0.25,-5.6) 26(0.75,-5.6) 27(1.25,-5.6) 28(1.75,-5.6) 29(2.25,-5.6) 30(2.75,-5.6) 31(3.25,-5.6) 32(3.75,-5.6) 49(3.75,5.6) 50(3.25,5.6) 51(2.75,5.6) 52(2.25,5.6) 53(1.75,5.6) 54(1.25,5.6) 55(0.75,5.6) 56(0.25,5.6) 57(-0.25,5.6) 58(-0.75,5.6) 59(-1.25,5.6) 60(-1.75,5.6) 61(-2.25,5.6) 62(-2.75,5.6) 63(-3.25,5.6) 64(-3.75,5.6)
  silkscreen extent -5.72,-4.15 4.15,4.57, body extent -5,-5 5,5, height 1.6
TEST_POINT_40_MIL-Footprint-1#1 [mil]
  round 40 smd: 1(3.94,0)
TEST_POINT_40_MIL-Footprint-1#2 [mil]
  round 40 smd: 1(0,0)
TPSM33625FRDNR [mm]
  rect 1.2x0.475 smd paste-0.587 mask-0.584: 1(-1.4,1.962) 8(1.4,1.962)
  rect 1.2x0.35 smd paste-0.587 mask-0.584: 2(-1.4,1.15) 3(-1.4,0.65) 6(1.4,0.65) 7(1.4,1.15)
  rect 1.6x2.15 smd paste-1.062 mask-1.067: 4(-1.2,-1) 5(1.2,-1)
  rect 0.35x0.9 smd paste-0.437 mask-0.432: 9(0.5,2.05) 11(-0.5,2.05)
  rect 0.504x0.504 smd paste-0.239 mask-0.241: 10(0,1.005)
  Top Layer region: -0.2,1.515 -0.2,2.4 -0.1,2.5 0.1,2.5 0.2,2.4 0.2,1.515 0.24,1.475 0.28,1.435 0.28,0.762 -0.28,0.762 -0.28,1.435 -0.24,1.475
  silkscreen extent -2.1,-2.42 2.1,2.6
TRACO-SIP-3_V [mm] "SIP, 3-Leads, Body 11.7x7.6mm, Pitch 2.54mm"
  rect 1.35x1.35 hole 0.85 paste-2539.97: 1(-2.54,0)
  round 1.35 hole 0.85 paste-2539.97: 2(0,0) 3(2.54,0)
  silkscreen extent -5.84,-2.77 5.86,5.6, body extent -5.84,-2 5.86,5.6, height 10.2
TSR1-SINGLE_TRP [mil]
  round 50 / inner round 60 / far side round 50 hole 30 paste-99999 mask+0: 1(0,0) 2(100,0) 3(200,0)
  silkscreen extent -220,-85 335,225
WL-SMCW_0603_150060xx75000 [mm] "SMD Mono-color Chip LED, body 1.60 x 0.80 mm"
  rect 0.8x0.8 smd: 1(-0.8,0) 2(0.8,0)
  silkscreen extent -1.55,-0.4 -1.4,0.4, body extent -0.8,-0.4 0.8,0.4, height 0.7

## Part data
C1 C3 C4 C5 C6 C7 C10 C13 C14 C17 C19 C21 C24 C32 C33 C37 C41 C43 C44 C45 C46 C48 C49 C50 C51 C53 C55 C56 C61 C63 C68_DATA C68_Drive: library part CMP-001-00125-1, "Ceramic Capacitor, Multilayer, Ceramic, 50V, 10% +Tol, 10% -Tol, X7R, 15% TC, 0.1uF, Surface Mount, 0603", Capacitor Type=Ceramic, Case/Package=0603, Max Operating Temperature=125°C, Min Operating Temperature=-55°C
C2 C18 C20 C52 C54 C60 C62 C67_DATA C67_Drive: library part CMP-001-00126-1, "Ceramic Capacitor, Multilayer, Ceramic, 35V, 10% +Tol, 10% -Tol, X5R, 15% TC, 4.7uF, Surface Mount, 0603", Capacitor Type=Ceramic, Case/Package=0603, Max Operating Temperature=85°C, Min Operating Temperature=-55°C
C8 C25 C27 C30 C35 C39 C40 C59 C66: library part CMP-001-00128-1, "Ceramic Capacitor, Multilayer, Ceramic, 50V, 10% +Tol, 10% -Tol, X5R, 15% TC, 1uF, Surface Mount, 0603", Capacitor Type=Ceramic, Case/Package=0603, Max Operating Temperature=85°C, Min Operating Temperature=-55°C
C9 C26 C28 C29 C31 C34 C38: library part CMP-001-00094-1, "Ceramic Capacitor, Ceramic, 1 nF, CL10B102KB8WPJC"
C11 C12: library part CMP-001-00113-1, "Ceramic Capacitor, Multilayer, Ceramic, 50V, 5% +Tol, 5% -Tol, C0G, -/+30ppm/Cel TC, 0.000015uF, Surface Mount, 0603", Capacitor Type=Ceramic, Case/Package=0603, Max Operating Temperature=125°C, Min Operating Temperature=-55°C
C15 C16: library part CMP-001-00112-1, "Ceramic Capacitor, Multilayer, Ceramic, 10V, 10% +Tol, 10% -Tol, X7S, 22% TC, 2.2uF, Surface Mount, 0603"
C22 C23: library part CMP-001-00103-1, "Ceramic Capacitor, Multilayer, Ceramic, 100V, 5% +Tol, 5% -Tol, C0G, -/+30ppm/Cel TC, 0.00022uF, Surface Mount, 0603", Capacitor Type=Ceramic, Case/Package=0603, Max Operating Temperature=125°C, Min Operating Temperature=-55°C
C36: library part CMP-001-00127-1, "Ceramic Capacitor, Multilayer, Ceramic, 100V, 10% +Tol, 10% -Tol, X7R, 15% TC, 0.01uF, Surface Mount, 0603", Capacitor Type=Ceramic, Case/Package=0603, Max Operating Temperature=125°C, Min Operating Temperature=-55°C
C42 C47: library part CMP-001-00133-1, "Ceramic Capacitor, Multilayer, Ceramic, 35V, 20% +Tol, 20% -Tol, X5R, 15% TC, 10uF, Surface Mount, 0603", Capacitor Type=Ceramic, Case/Package=0603, Max Operating Temperature=85°C, Min Operating Temperature=-55°C
C57 C58 C64 C65: library part CMP-001-00132-1, "Ceramic Capacitor, Multilayer, Ceramic, 25V, 20% +Tol, 20% -Tol, X5R, 15% TC, 22uF, Surface Mount, 0805", Capacitor Type=Ceramic, Case/Package=0805, Max Operating Temperature=85°C, Min Operating Temperature=-55°C
D1 D3: library part CMP-1426-00001-4, "LED Low-Power Uni-Color Red 630nm 2V 2-Pin Chip 0603(1608Metric) T/R", Case Code (Imperial)=0603, Case Code (Metric)=1608, Color=Red, Forward Current=100mA, Forward Voltage=2V, Max Junction Temperature (Tj)=95°C, Max Operating Temperature=85°C, Max Reverse Voltage (DC)=5V, Min Operating Temperature=-40°C, Power Dissipation=72mW, Test Current=20mA
D2 D4 D5 D6: library part CMP-1426-00005-3, "WL-SMCW SMT Mono-Color Chip LED Waterclear", Case Code (Imperial)=0603, Case Code (Metric)=1608, Color=Yellow, Forward Current=100mA, Forward Voltage=2V, Max Junction Temperature (Tj)=95°C, Max Operating Temperature=85°C, Max Reverse Voltage (DC)=5V, Min Operating Temperature=-40°C, Power Dissipation=72mW, Test Current=20mA
D7 D8: "TVS Diode (Bi-directional)", Manufacturer_Name=LITTELFUSE, Mouser Part Number=576-SD12C-01FTG
D9 D10: "Diode", Manufacturer_Name=Nexperia, Mouser Part Number=771-PMEG6010CEJ-T/R
D11 D12 D13: library part CMP-1426-00003-4, "Led, Blue, 470 Nm, 3.2 V, 30 Ma, 145 Mcd Rohs Compliant: Yes", Case Code (Imperial)=0603, Case Code (Metric)=1608, Color=Blue, Forward Current=100mA, Forward Voltage=3.2V, Max Junction Temperature (Tj)=95°C, Max Operating Temperature=85°C, Max Reverse Voltage (DC)=5V, Min Operating Temperature=-40°C, Power Dissipation=105mW, Test Current=20mA
D14: library part CMP-1426-00006-7, "WURTH ELEKTRONIK - 150060VS75000 - LED, Green, SMD, 0603, 30 mA, 2 V, 570 nm", Case Code (Imperial)=0603, Case Code (Metric)=1608, Color=Green, Forward Current=100mA, Forward Voltage=2V, Max Junction Temperature (Tj)=95°C, Max Operating Temperature=85°C, Max Reverse Voltage (DC)=5V, Min Operating Temperature=-40°C, Power Dissipation=72mW, Test Current=20mA
IC1: "Integrated Circuit", Manufacturer_Name=STMicroelectronics, Mouser Part Number=511-USBLC6-2SC6
IC2: "Integrated Circuit", Manufacturer_Name="Analog Devices", Mouser Part Number=584-ADBMS6822WCCSZ
IC3: "Integrated Circuit", Manufacturer_Name="Texas Instruments", Mouser Part Number=595-AMC3302DWE
IC4: "Integrated Circuit", Manufacturer_Name="Texas Instruments", Mouser Part Number=595-REF2025AIDDCR
J1: library part CMP-002-00103-1, "Board Connector, 15 Contact(s), 1 Row(s), Female, Straight, 0.059 inch Pitch, Surface Mount Terminal, Locking, Beige Insulator, Receptacle", Max Operating Temperature=85°C, Min Operating Temperature=-25°C
J2: "Connector", Manufacturer_Name="Wurth Elektronik", Mouser Part Number=710-61300611121
J3: "Connector", Arrow Part Number=DF11-4DP-2DSA(01), Manufacturer_Name=Hirose, Mouser Part Number=798-DF11-4DP-2DSA01
J4: library part CMP-002-00105-1, "Rectangular Power Connector, 4 Contact(s), Male, Surface Mount Terminal, Receptacle", Max Operating Temperature=105°C, Min Operating Temperature=-40°C
L1: library part CMP-06042-014671-1, "Wire Wound RF Inductor 39nH ±5% 400mA 0.26Ω 0603 (1608)", Case Code (Imperial)=0603, Case Code (Metric)=1608, Current Rating=400mA, DC Resistance (DCR)=260mR, Inductance=39nH, Max Operating Temperature=125°C, Min Operating Temperature=-55°C, Package Quantity=4000, Resistor Type=Wirewound, Self Resonant Frequency=2.8GHz, Test Frequency=100MHz, Tolerance=5%
MH1 MH2 MH3 MH4: library part CMP-00028-00008-4, "Mounting hole for 6-32 fastener"
P1: library part CMP-002-00079-1, "USB - micro B USB 2.0 Receptacle Connector 5 Position Surface Mount, Right Angle; Through Hole"
Q1 Q2 Q3 Q4 Q5 Q6: library part CMP-12801-000002-1, "MOSFET P-CH 30V 4.3A SOT23", Continuous Drain Current=-4.3A, Drain To Source Breakdown Voltage=-30V, Drain To Source Resistance=35mΩ, Gate To Source Voltage=25V, Input Capacitace At Vds="642pF @ -25V", Manufacturer="Diodes Inc.", Max Forward Diode Voltage=-1.2V, Max Junction Temp=+150°C, Package=SOT23, Power Dissipation=1.38W, Pulse Drain Current=-20A, Temperature="-55°C to +150°C", Temperature Range Low=-55°C
R1 R2: library part CMP-009-00242-1, "Fixed Resistor, Metal Glaze/thick Film, 0.1W, 22ohm, 75V, 1% +/-Tol, 100ppm/Cel, Surface Mount, 0603", Case/Package=0603, Max Operating Temperature=155°C, Min Operating Temperature=-55°C, Power=100mW, Tolerance=1%
R3 R15 R18 R30 R32 R37 R38 R41 R44 R45 R48 R49 R50 R51 R56 R59 R61: library part CMP-009-00204-1, "Fixed Resistor, Thin Film, 0.1W, 10000ohm, 75V, 0.1% +/-Tol, 25ppm/Cel, Surface Mount, 0603", Case/Package=0603, Max Operating Temperature=155°C, Min Operating Temperature=-55°C, Power=100mW, Tolerance=0.1%
R4 R5 R6 R33 R35: library part CMP-009-00257-1, "Fixed Resistor, Metal Glaze/thick Film, 0.1W, 10ohm, 75V, 1% +/-Tol, 100ppm/Cel, Surface Mount, 0603", Case/Package=0603, Max Operating Temperature=155°C, Min Operating Temperature=-55°C, Power=100mW, Tolerance=1%
R7 R29 R36 R39 R40 R42 R43 R46 R47 R52 R53 R58: library part CMP-009-00259-1, "Fixed Resistor, Thin Film, 0.1W, 47000ohm, 75V, 0.1% +/-Tol, 25ppm/Cel, Surface Mount, 0603", Case/Package=0603, Max Operating Temperature=155°C, Min Operating Temperature=-55°C, Power=100mW, Tolerance=0.1%
R8: library part CMP-009-00261-1, "Fixed Resistor, Thin Film, 0.1W, 6200ohm, 75V, 0.1% +/-Tol, 25ppm/Cel, Surface Mount, 0603", Case/Package=0603, Max Operating Temperature=155°C, Min Operating Temperature=-55°C, Power=100mW, Tolerance=0.1%
R9 R24 R25 R26 R27 R54: library part CMP-009-00243-1, "Fixed Resistor, Metal Glaze/thick Film, 0.1W, 0ohm, Surface Mount, 0603", Case/Package=0603, Max Operating Temperature=155°C, Min Operating Temperature=-55°C, Power=100mW
R10: library part CMP-009-00221-2, "Fixed Resistor, Metal Glaze/thick Film, 0.1W, 100000ohm, 75V, 1% +/-Tol, 100ppm/Cel, Surface Mount, 0603", Case/Package=0603, Max Operating Temperature=155°C, Min Operating Temperature=-55°C, Power=100mW, Tolerance=1%
R11: library part CMP-009-00220-2, "Fixed Resistor, Thin Film, 0.1W, 15000ohm, 75V, 0.1% +/-Tol, 25ppm/Cel, Surface Mount, 0603", Case/Package=0603, Max Operating Temperature=155°C, Min Operating Temperature=-55°C, Power=100mW, Tolerance=0.1%
R12 R13 R16 R17 R19 R31 R55: library part CMP-009-00263-1, "Fixed Resistor, Metal Glaze/thick Film, 0.1W, 1000ohm, 75V, 1% +/-Tol, 100ppm/Cel, Surface Mount, 0603", Case/Package=0603, Max Operating Temperature=155°C, Min Operating Temperature=-55°C, Power=100mW, Tolerance=1%
R14: library part CMP-009-00260-1, "Fixed Resistor, Thin Film, 0.1W, 3300ohm, 75V, 0.1% +/-Tol, 25ppm/Cel, Surface Mount, 0603", Case/Package=0603, Max Operating Temperature=155°C, Min Operating Temperature=-55°C, Power=100mW, Tolerance=0.1%
R20 R21 R22 R23: library part CMP-009-00206-1, "Fixed Resistor, Metal Glaze/thick Film, 0.25W, 47ohm, 150V, 5% +/-Tol, 200ppm/Cel, Surface Mount, 0603", Case/Package=0603, Max Operating Temperature=155°C, Min Operating Temperature=-55°C, Power=250mW, Tolerance=5%
R28 R34: library part CMP-009-00215-1, "Fixed Resistor, Thin Film, 0.1W, 20000ohm, 75V, 0.1% +/-Tol, 25ppm/Cel, Surface Mount, 0603", Case/Package=0603, Max Operating Temperature=155°C, Min Operating Temperature=-55°C, Power=100mW, Tolerance=0.1%
R57: library part CMP-009-00267-1, "Fixed Resistor, Thin Film, 0.1W, 23200ohm, 75V, 0.1% +/-Tol, 25ppm/Cel, Surface Mount, 0603", Case/Package=0603, Max Operating Temperature=155°C, Min Operating Temperature=-55°C, Power=100mW, Tolerance=0.1%
R60: library part CMP-009-00266-1, "Fixed Resistor, Thin Film, 0.1W, 40200ohm, 75V, 0.1% +/-Tol, 25ppm/Cel, Surface Mount, 0603", Case/Package=0603, Max Operating Temperature=155°C, Min Operating Temperature=-55°C, Power=100mW, Tolerance=0.1%
R62_DATA R62_Drive: library part CMP-009-00223-1, "Fixed Resistor, Metal Glaze/thick Film, 0.1W, 120ohm, 75V, 1% +/-Tol, 100ppm/Cel, Surface Mount, 0603, RMCF0603FT120R", Case/Package=0603, Max Operating Temperature=155°C, Min Operating Temperature=-55°C, Power=100mW, Tolerance=1%
T1: "Transformer", Manufacturer_Name="Wurth Elektronik"
TP1 TP2 TP3 TP4 TP5: library part CMP-001-0000-1, "40 mil diameter test point"
U1: library part CMP-0859-00206-4, "IC TRNSLTR BIDIRECTIONAL SOT23-6", Case/Package=SOT-23, High Level Output Current=-32mA, Low Level Output Current=32mA, Max Operating Temperature=85°C, Max Supply Voltage=5.5V, Min Operating Temperature=-40°C, Min Supply Voltage=1.65V, Package Quantity=3000, Quiescent Current=3uA
U2: library part CMP-0243-00019-3, "ARM Cortex-M4 32-bit MCU+FPU, 210 DMIPS, 1024 kB Flash, 192 kB Internal RAM, 51 I/Os, 64-pin LQFP, -40 to 85 degC, Tray", I/Os (High Current)=51, Manufacturer=STMicroelectronics, Operating Frequency(F) (Processor speed) (MHz)=168, Supply Voltage(Vcc) max (V)=3.6, Supply Voltage(Vcc) min (V)=1.8
U3: library part CMP-0272-00853-3, "Precision, 20 MHz, 0.9 pA Ib, RRIO, CMOS Operational Amplifier, 1.8 to 5.5 V, -40 to 125 degC, 5-pin SOT23 (DBV5), Green (RoHS & no Sb/Br)", Manufacturer="Texas Instruments", Total Supply Voltage(Max)(+5V is 5, +/-5V is 10)=5.5, Total Supply Voltage(Min)(+5V is 5, +/-5V is 10)=1.8
U4 U5 U6 U7: library part CMP-011-000000-2, "N-CH MOSFET", Mfr_Name="Diodes Inc"
U8: library part CMP-2000-05426-2, Case/Package=SIP, Max Input Voltage=36V, Max Input Voltage (DC)=32V, Max Operating Temperature=85°C, Max Output Current=1A, Max Output Power=3.3W, Min Input Voltage=4.75V, Min Input Voltage (DC)=5.5V, Min Operating Temperature=-40°C, Nominal Output Voltage=3.3V, Nominal Supply Current=1mA, Switching Frequency=500kHz
U9 U11: "No Description Available", Mfr_Name="Texas Instruments"
U10: library part CMP-2000-05427-1, "DC/DC converter, 5 VDC, 1000 mA, -40 to 85 degC, 3-Pin SIP, RoHS", Input Voltage DC Max=36V, Input Voltage DC Min=6.5V, Manufacturer=Tracopower, Output Current Max=1A, Output Power Max=5W, Output Voltage Nom.=5V, Package Description="3-Pin Single In-line Package, Body 11.7 x 7.6 mm, Pitch 2.54 mm", Package Reference=SIP-3
U12_DATA U12_Drive: library part CMP-05676-000001-1, "IC TXRX CAN 1MBPS 8-SOIC", Manufacturer="Maxim Integrated", Max Junction Temp=+150°C, Max Supply Voltage=3.47V, Min Supply Voltage=3.14V, Nominal Supply Current=8-35000uA, Package=S8-4, Temperature="-40°C to +85°C", Temperature Range High=+85°C, Temperature Range Low=-40°C
Y1: library part CMP-2000-05730-2, "Crystal 8MHz ±10ppm 10pF SMD-4 5mm x 3.2mm", Case/Package=SMD/SMT, ESR (Equivalent Series Resistance)=200R, Frequency=8MHz, Frequency Stability=10ppm, Load Capacitance=10pF, Max Operating Temperature=60°C, Min Operating Temperature=-10°C

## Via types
v1: diameter 0.45, hole 0.2, Top Layer to Bottom Layer, tented both sides, 364 vias
v2: diameter 1, hole 0.5, Top Layer to Bottom Layer, tented both sides, 12 vias

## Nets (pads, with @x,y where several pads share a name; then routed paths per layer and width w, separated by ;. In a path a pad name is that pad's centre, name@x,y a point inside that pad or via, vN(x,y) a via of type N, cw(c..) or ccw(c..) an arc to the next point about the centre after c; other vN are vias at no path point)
1V25: C39.2 IC4.1 R34.1 | length 3.4
  Top Layer w0.5: IC4.1@88.6,64.5 88.696,64.5 88.7,64.496 C39.2@88.7,62.95 ; C39.2@88.7,62.9 88.78,62.82 88.78,62.62 89.67,61.73 89.72,61.73 89.8,61.65 R34.1@89.8,61.6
